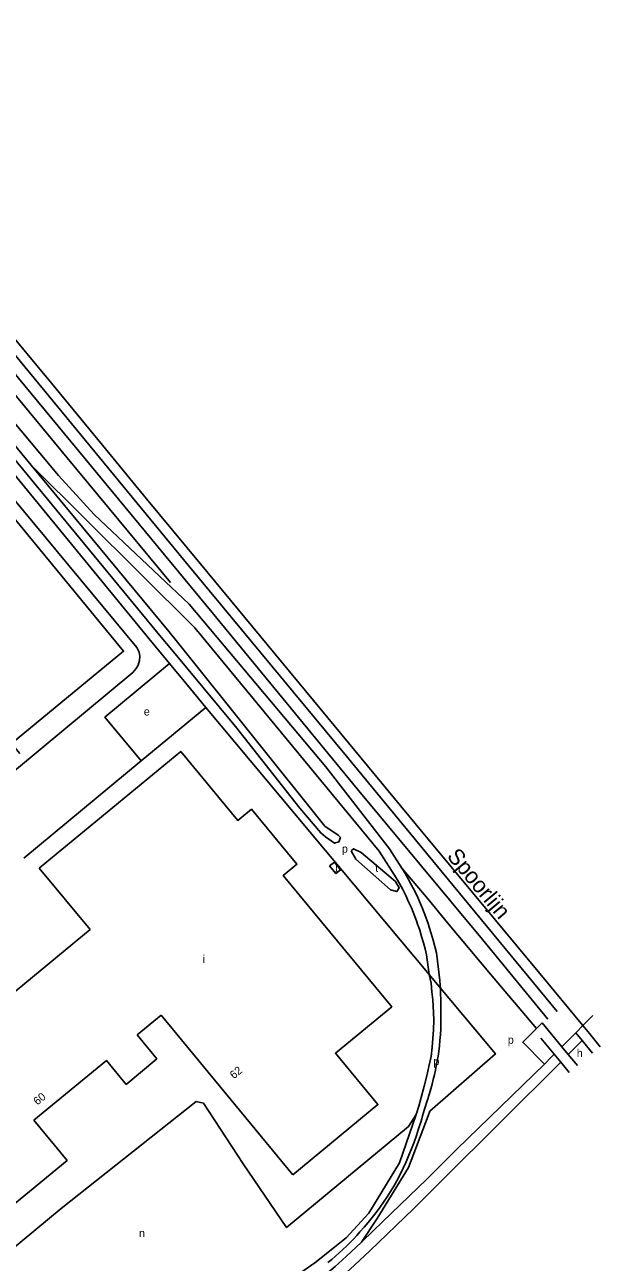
# Model space of a CAD drawing. Extents: x 156097 to 158136, y 385644 to 388348.
# Drawn here: x 157848 to 158136, y 386543 to 387162 of the extents above; entities that cross this region are included whole.
import ezdxf

# ---------------------------------------------------------------- set-up
doc = ezdxf.new("R2010")
doc.units = 0
for name, color, linetype in [('BLT_Basislijn', 7, 'Continuous'), ('BLT_Bebouwing', 7, 'Continuous'), ('BLT_Centroide', 7, 'Continuous'), ('BLT_Huisnummer_reeks', 7, 'Continuous'), ('BLT_Spoorlijn', 7, 'Continuous'), ('BLT_Vlakafsluiter', 7, 'Continuous'), ('BLT_Waternaam_spoorwegen', 7, 'Continuous')]:
    doc.layers.add(name, color=color, linetype=linetype)

msp = doc.modelspace()

# ---------------------------------------------------------------- linework, layer by layer
at = {"layer": 'BLT_Basislijn'}
for p, q in [((157751.06, 387063.19), (157851.57, 386941.79)), ((157938.9, 386820.64), (158050.53, 386687.09)), ((158036.94, 386740.31), (158050, 386724.65)), ((158050, 386724.65), (158059.73, 386712.97)), ((158059.73, 386712.97), (158081.15, 386687.29)), ((158050.53, 386687.09), (158056.22, 386680.28)), ((158081.15, 386687.29), (158104.21, 386660.05)), ((158107, 386662.83), (158104.21, 386660.05)), ((158116.83, 386650.96), (158107, 386662.83)), ((158103.25, 386659.08), (158104.21, 386660.05)), ((158116.83, 386650.96), (158123.83, 386657.96)), ((158127.11, 386653.98), (158123.83, 386657.96)), ((158113.08, 386647.21), (158106.44, 386655.23)), ((158120.11, 386647.01), (158116.83, 386650.96)), ((158120.11, 386647.01), (158127.11, 386653.98)), ((158132.22, 386647.76), (158127.11, 386653.98)), ((158111.69, 386645.82), (158113.08, 386647.21)), ((158116.35, 386643.27), (158113.08, 386647.21)), ((158124.66, 386641.51), (158120.11, 386647.01)), ((158056.57, 386583.73), (158116.35, 386643.27)), ((158064.41, 386599.72), (158108.16, 386642.28)), ((158120.61, 386638.12), (158116.35, 386643.27)), ((158050, 386577.19), (158056.57, 386583.73)), ((157866.58, 386570.02), (157779.9, 386498.42))]:
    msp.add_line(p, q, dxfattribs=at)
for points in [[(157851.57, 386941.79), (157920.62, 386858.39), (157924.71, 386853.26), (157998.42, 386761.3), (158005.01, 386756.81), (158006.22, 386755.55), (158005.44, 386753.42), (158003.29, 386752.72), (157998.79, 386755.83), (157996.35, 386757.83), (157986, 386770.15), (157953.74, 386811.03), (157921.18, 386850.38), (157916.63, 386855.8), (157797.28, 387000.37), (157759.87, 387044.9)], [(157791.14, 386997.15), (157791.47, 386997.08), (157792.33, 386996.8), (157793.15, 386996.46), (157793.95, 386996.04), (157794.7, 386995.55), (157795.41, 386994.99), (157796.06, 386994.38), (157796.66, 386993.71), (157805.65, 386982.75), (157910.4, 386855.07), (157920.8, 386842.5)], [(157796.67, 386980.47), (157904.51, 386850.54), (157905.67, 386848.15), (157905.9, 386846.12), (157905.85, 386844), (157905.07, 386841.79), (157904.05, 386840.13), (157902.53, 386838.1), (157832.25, 386779.84)], [(157851.57, 386941.79), (157933.36, 386860.36), (158025.58, 386748.8)], [(157906.63, 386793.85), (157888.5, 386815.69), (157920.8, 386842.5)], [(157920.8, 386842.5), (157928.94, 386832.67)], [(157938.9, 386820.64), (157928.94, 386832.67)], [(157906.63, 386793.85), (157938.9, 386820.64)], [(157847.99, 386745.18), (157906.63, 386793.85)], [(158025.58, 386748.8), (158034.14, 386735.4), (158035.75, 386732.52), (158037.33, 386729.52), (158038.85, 386726.48), (158040.31, 386723.42), (158041.68, 386720.36), (158043.41, 386716.09), (158044.21, 386713.95), (158044.98, 386711.8), (158045.25, 386710.99), (158045.85, 386709.18), (158046.82, 386706.05), (158047.73, 386702.96), (158048.52, 386699.85), (158049.25, 386696.93), (158050.53, 386687.09)], [(158044.14, 386617.05), (158045.37, 386621.17), (158046.62, 386625.59), (158048.05, 386631.17), (158049.38, 386636.47), (158050.44, 386641.03), (158051.5, 386646.1), (158052.1, 386650.8), (158052.47, 386655), (158052.66, 386659.38), (158052.89, 386664.22), (158052.79, 386668.04), (158052.56, 386671.27), (158052.33, 386674.45), (158051.96, 386678.36), (158051.55, 386682.7), (158050.53, 386687.09)], [(158056.22, 386680.28), (158083.72, 386647.38), (158050.84, 386618.71), (158050, 386616.46)], [(158103.25, 386659.08), (158097.31, 386653.16), (158108.16, 386642.28)], [(157866.58, 386570.02), (157934.11, 386623.48), (157937.81, 386622.68), (157957.67, 386592.46), (157979.26, 386560.56), (158040.17, 386611.05), (158044.14, 386617.05)], [(158044.14, 386617.05), (158035.78, 386592.84), (158020.34, 386567.65), (158009.01, 386555.36), (157993.44, 386542.83), (157975.44, 386530.4), (157945.11, 386512.31), (157901.03, 386491), (157848.87, 386468.63)], [(158050, 386616.46), (158040.29, 386590.64), (158024.62, 386565.07), (158016.72, 386553.31)], [(158016.72, 386553.31), (158022.8, 386559.11), (158049.37, 386584.74), (158052.57, 386587.91), (158064.41, 386599.72)], [(158020.85, 386548.96), (158042.7, 386569.93), (158050, 386577.19)], [(157937.31, 386498.26), (157963.77, 386512.3), (157974.11, 386518.81), (157987.54, 386528.29), (157996.13, 386534.66), (158003.64, 386541.12), (158009.16, 386546.14), (158016.72, 386553.31)], [(157992.83, 386524.14), (158000, 386530.08), (158007.62, 386536.62), (158013.24, 386541.75), (158020.85, 386548.96)]]:
    msp.add_lwpolyline(points, dxfattribs=at)
msp.add_lwpolyline([(158011.57, 386748.86), (158012.73, 386749.95), (158016.52, 386748), (158033.82, 386733.5), (158035.65, 386730.32), (158034.48, 386728.55), (158031.19, 386729.37), (158013.92, 386744.67)], close=True, dxfattribs=at)
at = {"layer": 'BLT_Bebouwing'}
for p, q in [((157881.08, 386709.55), (157855.71, 386740.27)), ((157904.6, 386656.85), (157916.53, 386666.69)), ((157916.53, 386666.69), (157982.39, 386586.88)), ((157914.51, 386644.84), (157904.6, 386656.85)), ((157899.12, 386632.14), (157914.51, 386644.84))]:
    msp.add_line(p, q, dxfattribs=at)
for points in [[(157715.12, 386921.18), (157713, 386923.77), (157718.92, 386928.68), (157721.23, 386925.9), (157726.97, 386930.65), (157730.47, 386926.43), (157791.99, 386977.22), (157897.82, 386848.71), (157841.85, 386802.62), (157845.97, 386797.62)], [(157855.71, 386740.27), (157926.39, 386798.63), (157954.91, 386764.09), (157961.69, 386769.68), (157984.43, 386742.15), (157977.66, 386736.54), (158031.85, 386670.96), (158003.69, 386647.68), (158024.92, 386621.98), (157982.39, 386586.88)], [(157853.01, 386614.18), (157869.58, 386594.14), (157831.83, 386562.98), (157767.95, 386640.37), (157760.86, 386634.52), (157756.41, 386639.61), (157763.75, 386646.04), (157773.08, 386654.92), (157778.56, 386649.15), (157798.69, 386665.79), (157810.89, 386651.57), (157881.08, 386709.55)], [(157853.01, 386614.18), (157889.22, 386644.13), (157899.12, 386632.14)]]:
    msp.add_lwpolyline(points, dxfattribs=at)
msp.add_lwpolyline([(158000.83, 386741.4), (158003.94, 386737.5), (158006.29, 386739.36), (158003.18, 386743.25)], close=True, dxfattribs=at)
at = {"layer": 'BLT_Spoorlijn'}
for points in [[(158114.59, 386668.56), (158068.11, 386724.83), (158009.23, 386796.18), (157930.12, 386891.81), (157831.9, 387010.77), (157721.95, 387143.82), (157638.68, 387244.6), (157584.2, 387310.67), (157545.08, 387357.98), (157505.83, 387405.66)], [(157628.61, 387250), (157717.05, 387140.23), (157834.82, 386997.8), (157942.16, 386868.13), (158014.56, 386779.96), (158077.18, 386704.5), (158109.93, 386664.79)], [(157672.34, 387183.89), (157707.12, 387141.67), (157740.15, 387090), (157808.39, 387004.56), (157865.24, 386936.61), (157883.2, 386917.03), (157930.67, 386872.31), (157998.86, 386790.82), (158030.8, 386749.92)], [(157921.28, 386883.11), (157869.68, 386945.42), (157783.98, 387048.91), (157712.28, 387136)], [(157836.71, 387013.06), (157861.73, 386982.75)], [(157861.73, 386982.75), (157887.29, 386951.79)], [(157887.29, 386951.79), (157909.21, 386924.84)], [(157909.21, 386924.84), (157936.15, 386892.56)], [(157936.15, 386892.56), (157999.88, 386815.47)], [(157999.88, 386815.47), (158046.7, 386758.74)], [(158046.7, 386758.74), (158050, 386754.78)], [(158030.8, 386749.92), (158036.94, 386740.31)], [(158050, 386754.78), (158105.89, 386687.6)], [(158056.22, 386680.28), (158056.13, 386681.67), (158055.96, 386684.04), (158054.18, 386697.86), (158053.37, 386701.07), (158052.56, 386704.28), (158051.61, 386707.49), (158050.61, 386710.71), (158050, 386712.56), (158049.71, 386713.43), (158048.9, 386715.67), (158048.07, 386717.91), (158047.18, 386720.11), (158046.28, 386722.32), (158044.85, 386725.51), (158043.35, 386728.67), (158041.78, 386731.8), (158040.14, 386734.9), (158038.44, 386737.96), (158036.94, 386740.31)], [(158105.89, 386687.6), (158127.38, 386661.51)], [(158056.22, 386680.28), (158056.29, 386679.31), (158056.36, 386672.95), (158056.4, 386665.26), (158056.33, 386659.95), (158056.16, 386657.02), (158055.96, 386654.13), (158055.67, 386651.32), (158055.38, 386648.51)], [(158127.38, 386661.51), (158130.66, 386657.52)], [(158130.66, 386657.52), (158136.08, 386650.94)], [(158055.38, 386648.51), (158055, 386646.16), (158054.6, 386643.82), (158054.15, 386641.48), (158053.67, 386639.15), (158053.16, 386636.83), (158052.61, 386634.51), (158052.02, 386632.21), (158051.4, 386629.91), (158050.75, 386627.62)], [(158050, 386625.19), (158049.77, 386624.44), (158049.28, 386622.84), (158048.79, 386621.25), (158048.3, 386619.65), (158047.81, 386618.06), (158047.32, 386616.46), (158046.83, 386614.87), (158046.34, 386613.28)], [(158050.75, 386627.62), (158050.26, 386626.03), (158050, 386625.19)], [(158046.34, 386613.28), (158045.3, 386609.91), (158044.18, 386606.57), (158042.99, 386603.25), (158041.74, 386599.95), (158040.41, 386596.68), (158039.02, 386593.44), (158037.55, 386590.23), (158036.02, 386587.05), (158034.43, 386583.91), (158032.88, 386581.21)], [(158032.88, 386581.21), (158031.24, 386578.5), (158029.55, 386575.84), (158027.79, 386573.21), (158025.97, 386570.62), (158024.09, 386568.07), (158022.15, 386565.57), (158020.15, 386563.11), (158018.1, 386560.71), (158015.99, 386558.35)], [(158015.99, 386558.35), (158014.35, 386556.52), (158012.67, 386554.72), (158010.95, 386552.95), (158009.2, 386551.21), (158007.42, 386549.5), (158005.61, 386547.83), (158003.77, 386546.19), (158001.9, 386544.58), (158000, 386543.01)]]:
    msp.add_lwpolyline(points, dxfattribs=at)
at = {"layer": 'BLT_Vlakafsluiter'}
for p, q in [((158132.44, 386666.58), (158127.38, 386661.51)), ((158127.38, 386661.51), (158123.83, 386657.96)), ((158108.16, 386642.28), (158111.69, 386645.82))]:
    msp.add_line(p, q, dxfattribs=at)

# ---------------------------------------------------------------- texts
at = {"layer": 'BLT_Centroide'}
for s, p in [('e', (157907.94, 386816.54)), ('p', (158006.94, 386747.96)), ('b', (158003.56, 386738.38)), ('t', (158023.59, 386738.38)), ('i', (157937.29, 386692.75)), ('p', (158089.87, 386652.41)), ('h', (158124.36, 386645.81)), ('p', (158052.7, 386641.74)), ('n', (157905.52, 386555.77))]:
    msp.add_text(s, height=4, dxfattribs=at).set_placement(p)
at = {"layer": 'BLT_Huisnummer_reeks'}
for s, p in [('62', (157952.95, 386634.64)), ('60', (157854.78, 386621.5))]:
    msp.add_text(s, height=4, rotation=39.58157, dxfattribs=at).set_placement(p)
at = {"layer": 'BLT_Waternaam_spoorwegen'}
msp.add_text('Spoorlijn', height=8, rotation=309.85737, dxfattribs=at).set_placement((158059.06, 386746.01))

doc.saveas('drawing.dxf')
